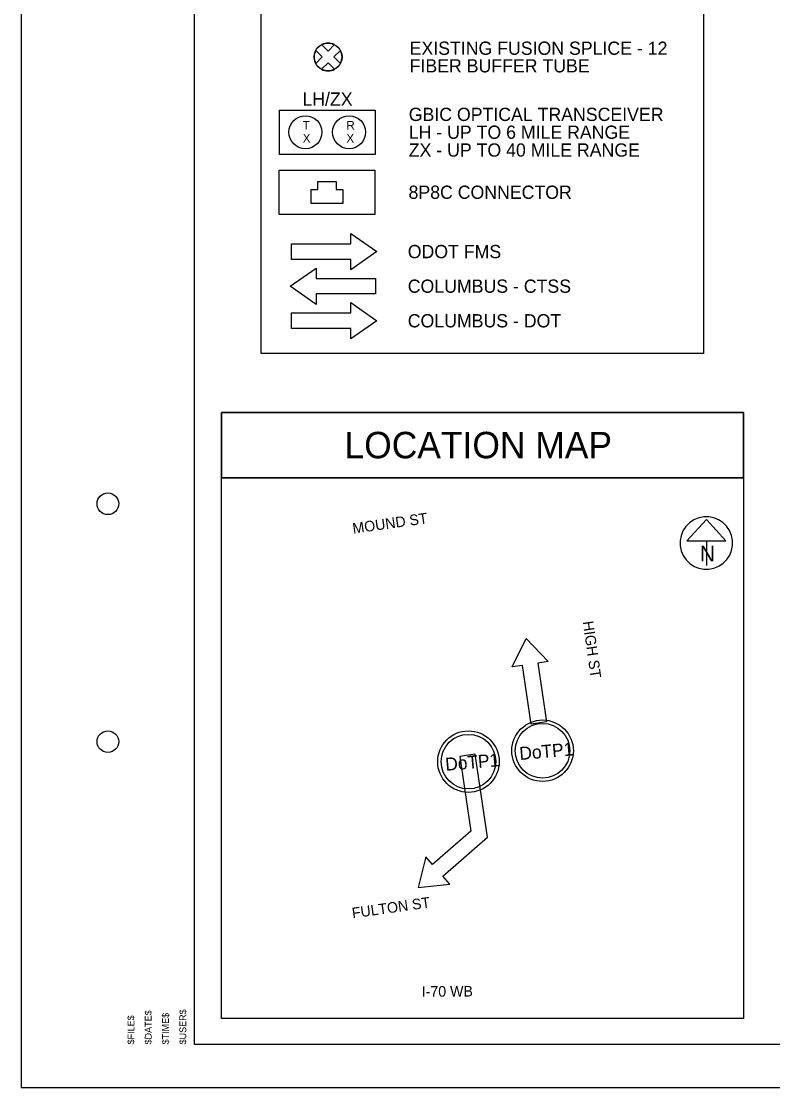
# Model space of a CAD drawing. Extents: x 1805893 to 1833564, y 708898 to 716199.
# Drawn here: x 1831322.5 to 1831496.1, y 715255.2 to 715501.7 of the extents above; entities that cross this region are included whole.
import ezdxf

# ---------------------------------------------------------------- set-up
doc = ezdxf.new("R2010")
doc.units = 0
for name, color, linetype in [('BR_X_Slab_Object', 7, 'Continuous'), ('SH_Border', 7, 'Continuous'), ('SH_Cut_Line', 7, 'Continuous'), ('SH_Data', 7, 'Continuous'), ('SH_Text', 7, 'Continuous'), ('UT_X_Misc_Cells', 7, 'Continuous')]:
    doc.layers.add(name, color=color, linetype=linetype)

msp = doc.modelspace()

# ---------------------------------------------------------------- linework, layer by layer
at = {"layer": 'SH_Border'}
msp.add_lwpolyline([(1831362.49, 715685.17), (1831992.49, 715685.17), (1831992.49, 715265.17), (1831362.49, 715265.17)], close=True, dxfattribs=at)
for centre in [(1831342.49, 715390.17), (1831342.49, 715335.17)]:
    msp.add_circle(centre, 2.5, dxfattribs=at)
at = {"layer": 'SH_Cut_Line'}
msp.add_lwpolyline([(1831322.49, 715255.17), (1832002.49, 715255.17), (1832002.49, 715695.17), (1831322.49, 715695.17)], close=True, dxfattribs=at)
at = {"layer": 'SH_Data'}
for p, q in [((1831393.39, 715494.83), (1831391.9, 715496.32)), ((1831391.9, 715496.32), (1831393.39, 715494.83)), ((1831393.39, 715494.83), (1831394.88, 715496.32)), ((1831393.39, 715494.83), (1831394.88, 715496.32)), ((1831392.03, 715493.47), (1831390.54, 715494.96)), ((1831392.03, 715493.47), (1831390.54, 715494.96)), ((1831390.54, 715491.98), (1831392.03, 715493.47)), ((1831390.54, 715491.98), (1831392.03, 715493.47)), ((1831394.75, 715493.47), (1831396.24, 715494.96)), ((1831396.24, 715494.96), (1831394.75, 715493.47)), ((1831396.24, 715491.98), (1831394.75, 715493.47)), ((1831394.75, 715493.47), (1831396.24, 715491.98)), ((1831391.9, 715490.62), (1831393.39, 715492.11)), ((1831393.39, 715492.11), (1831391.9, 715490.62)), ((1831394.88, 715490.62), (1831393.39, 715492.11)), ((1831394.88, 715490.62), (1831393.39, 715492.11)), ((1831398.67, 715450.28), (1831398.67, 715452.68)), ((1831384.93, 715450.28), (1831398.67, 715450.28)), ((1831384.93, 715446.68), (1831384.93, 715450.28)), ((1831398.67, 715446.68), (1831384.93, 715446.68)), ((1831398.67, 715444.28), (1831398.67, 715446.68)), ((1831390.6, 715444.68), (1831390.6, 715442.28)), ((1831390.6, 715442.28), (1831404.34, 715442.28)), ((1831404.34, 715442.28), (1831404.34, 715438.68)), ((1831404.34, 715438.68), (1831390.6, 715438.68)), ((1831390.6, 715438.68), (1831390.6, 715436.28)), ((1831398.67, 715434.28), (1831398.67, 715436.68)), ((1831384.93, 715434.28), (1831398.67, 715434.28)), ((1831384.93, 715430.68), (1831384.93, 715434.28)), ((1831398.67, 715430.68), (1831384.93, 715430.68)), ((1831398.67, 715428.28), (1831398.67, 715430.68))]:
    msp.add_line(p, q, dxfattribs=at)
for points in [[(1831480.16, 715615.12), (1831480.16, 715424.95), (1831377.93, 715424.95), (1831377.93, 715615.12)], [(1831382.14, 715481.21), (1831404.23, 715481.21), (1831404.23, 715470.96), (1831382.14, 715470.96)], [(1831382.08, 715467.33), (1831404.18, 715467.33), (1831404.18, 715457.08), (1831382.08, 715457.08)], [(1831489.36, 715411.3), (1831368.72, 715411.3), (1831368.72, 715396.18), (1831489.36, 715396.18)], [(1831489.36, 715396.18), (1831368.72, 715396.18), (1831368.72, 715411.3), (1831489.36, 715411.3)], [(1831489.36, 715396.18), (1831489.36, 715271.17), (1831368.72, 715271.17), (1831368.72, 715396.18)], [(1831489.36, 715396.18), (1831489.36, 715271.17), (1831368.72, 715271.17), (1831368.72, 715396.18)], [(1831489.36, 715396.18), (1831489.36, 715271.17), (1831368.72, 715271.17), (1831368.72, 715396.18)], [(1831489.36, 715396.18), (1831489.36, 715271.17), (1831368.72, 715271.17), (1831368.72, 715396.18)], [(1831489.36, 715396.18), (1831489.36, 715271.17), (1831368.72, 715271.17), (1831368.72, 715396.18)], [(1831489.36, 715396.18), (1831489.36, 715271.17), (1831368.72, 715271.17), (1831368.72, 715396.18)]]:
    msp.add_lwpolyline(points, close=True, dxfattribs=at)
for points in [[(1831391, 715462.81), (1831391, 715464.72), (1831395.25, 715464.72), (1831395.25, 715462.81)], [(1831395.25, 715462.81), (1831396.76, 715462.81), (1831396.76, 715459.58), (1831389.49, 715459.58), (1831389.49, 715462.81), (1831391, 715462.81)], [(1831398.67, 715452.68), (1831404.67, 715448.48), (1831398.67, 715444.28)], [(1831390.6, 715436.28), (1831384.6, 715440.48), (1831390.6, 715444.68)], [(1831398.67, 715436.68), (1831404.67, 715432.48), (1831398.67, 715428.28)]]:
    msp.add_lwpolyline(points, dxfattribs=at)
for centre, radius in [((1831393.39, 715493.47), 3.22), ((1831388.14, 715476.08), 3.81), ((1831398.23, 715476.08), 3.81)]:
    msp.add_circle(centre, radius, dxfattribs=at)
for start, end in [(62.353, 117.647), (152.353, 207.647), (332.353, 27.647), (242.353, 297.647)]:
    msp.add_arc((1831393.39, 715493.47), 3.22, start, end, dxfattribs=at)
at = {"layer": 'SH_Text'}
for p, q in [((1831480.81, 715386.57), (1831476.31, 715381.57)), ((1831485.32, 715381.57), (1831480.81, 715386.57)), ((1831476.31, 715381.57), (1831485.32, 715381.57)), ((1831480.81, 715381.57), (1831480.81, 715375.9)), ((1831438.3, 715352.79), (1831435.93, 715352.44)), ((1831440.32, 715339.2), (1831438.3, 715352.79)), ((1831444.23, 715353.67), (1831441.86, 715353.32)), ((1831441.86, 715353.32), (1831443.88, 715339.73)), ((1831443.88, 715339.73), (1831440.32, 715339.2)), ((1831427.4, 715332.24), (1831423.84, 715331.71)), ((1831423.84, 715331.71), (1831426.4, 715314.51)), ((1831430.25, 715313.1), (1831427.4, 715332.24)), ((1831426.4, 715314.51), (1831417.55, 715306.74)), ((1831419.93, 715304.03), (1831430.25, 715313.1)), ((1831417.55, 715306.74), (1831415.97, 715308.54)), ((1831421.51, 715302.23), (1831419.93, 715304.03))]:
    msp.add_line(p, q, dxfattribs=at)
for points in [[(1831435.93, 715352.44), (1831439.2, 715358.99), (1831444.23, 715353.67)], [(1831415.97, 715308.54), (1831414.24, 715301.42), (1831421.51, 715302.23)]]:
    msp.add_lwpolyline(points, dxfattribs=at)
for centre, radius in [((1831442.96, 715333.07), 7.11), ((1831442.96, 715333.07), 6.31), ((1831425.83, 715330.55), 7.11), ((1831425.83, 715330.55), 6.31)]:
    msp.add_circle(centre, radius, dxfattribs=at)
msp.add_arc((1831480.81, 715381.09), 6.08, 129.7798, 129.7633, dxfattribs=at)

# ---------------------------------------------------------------- texts
at = {"layer": 'BR_X_Slab_Object'}
for s, p in [('T', (1831387.53, 715476.68)), ('R', (1831397.63, 715476.68)), ('X', (1831387.53, 715473.68)), ('X', (1831397.63, 715473.68))]:
    msp.add_text(s, height=2, rotation=0.0475, dxfattribs=at).set_placement(p)
at = {"layer": 'SH_Data'}
for s, height, p in [('EXISTING FUSION SPLICE - 12 ', 3.0596, (1831412.24, 715493.97)), ('FIBER BUFFER TUBE', 3.0596, (1831412.24, 715489.9)), ('LH/ZX', 3.06, (1831387.45, 715482.21)), ('GBIC OPTICAL TRANSCEIVER', 3.0596, (1831412.03, 715478.67)), ('LH - UP TO 6 MILE RANGE', 3.0596, (1831412.03, 715474.55)), ('ZX - UP TO 40 MILE RANGE', 3.0596, (1831412.03, 715470.43)), ('8P8C CONNECTOR', 3.0596, (1831411.98, 715460.67)), ('ODOT FMS', 3.06, (1831411.8, 715446.95)), ('COLUMBUS - CTSS', 3.0596, (1831411.8, 715438.95)), ('COLUMBUS - DOT', 3.0596, (1831411.8, 715430.95)), ('LOCATION MAP', 6.1191, (1831397.18, 715400.68))]:
    msp.add_text(s, height=height, dxfattribs=at).set_placement(p)
at = {"layer": 'SH_Text'}
for s, height, rotation, p in [('MOUND ST', 2.448, 8.061, (1831399.21, 715383.24)), ('N', 3.66, 360, (1831479.29, 715376.83)), ('HIGH ST', 2.448, 278.061, (1831452.24, 715362.89)), ('DoTP1', 3, 5, (1831437.73, 715330.92)), ('DoTP1', 3, 5, (1831420.6, 715328.41)), ('FULTON ST', 2.448, 8.061, (1831399.08, 715294.31)), ('I-70 WB', 2.448, 0.3445, (1831415.04, 715276.18))]:
    msp.add_text(s, height=height, rotation=rotation, dxfattribs=at).set_placement(p)
at = {"layer": 'UT_X_Misc_Cells'}
for s, p in [('$FILE$', (1831348.59, 715265.16)), ('$DATE$', (1831352.59, 715265.16)), ('$TIME$', (1831356.59, 715265.16)), ('$USER$', (1831360.59, 715265.16))]:
    msp.add_text(s, height=1.56, rotation=90, dxfattribs=at).set_placement(p)

doc.saveas('drawing.dxf')
